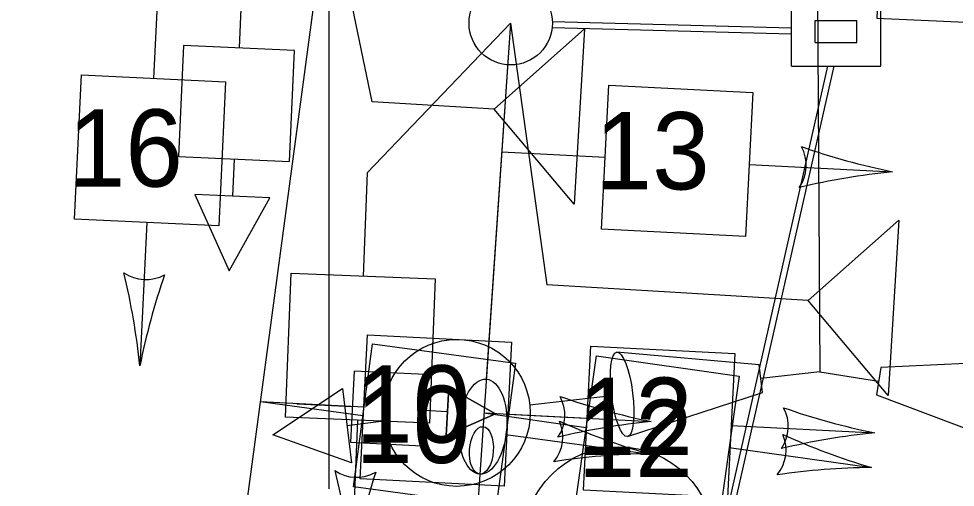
# Model space of a CAD drawing. Extents: x 647787 to 668496, y 640478 to 654412.
# Drawn here: x 659823.61 to 659862.98, y 647466.77 to 647486.47 of the extents above; entities that cross this region are included whole.
import ezdxf

# ---------------------------------------------------------------- set-up
doc = ezdxf.new("R2010")
doc.units = 0
for name, color, linetype in [('T_EXIST SIGNAL HEAD', 7, 'Continuous'), ('TEMP_SIGNAL POLES', 7, 'Continuous'), ('TEMP_SIGNAL_HEAD_STAGE 1A', 7, 'Continuous'), ('TEMP_SIGNAL_HEAD_STAGE 2', 7, 'Continuous'), ('TEMP_SIGNAL_HEAD_STAGE 2 SALEM', 7, 'Continuous'), ('TEMP_SIGNAL_HEAD_Stage 3', 7, 'Continuous'), ('TEMP_SIGNAL_HEAD_STAGE 5', 7, 'Continuous'), ('TEMP_SIGNAL_POLES_STAGE 1A', 7, 'Continuous'), ('TEMP_SIGNAL_POLES_STAGE 2', 7, 'Continuous'), ('TEMP_SIGNAL_POLES_STAGE 3', 7, 'Continuous'), ('TEMP_SIGNAL_POLES_STAGE 5', 7, 'Continuous'), ('TEXT_TEMP_SIGNAL_POLES_STAGE 2', 7, 'Continuous'), ('TEXT_TEMP_SIGNAL_POLES_STAGE 3', 7, 'Continuous'), ('TEXT_TEMP_SIGNAL_POLES_STAGE 4', 7, 'Continuous'), ('TEXT_TEMP_SIGNAL_POLES_STAGE 5', 7, 'Continuous')]:
    doc.layers.add(name, color=color, linetype=linetype)

msp = doc.modelspace()

# ---------------------------------------------------------------- linework, layer by layer
at = {"layer": 'T_EXIST SIGNAL HEAD'}
for points in [[(659837.714, 647471.654), (659837.562, 647468.658), (659840.558, 647468.506), (659840.71, 647471.502)], [(659837.714, 647471.654), (659837.562, 647468.658), (659840.558, 647468.506), (659840.71, 647471.502)], [(659837.714, 647471.654), (659837.562, 647468.658), (659840.558, 647468.506), (659840.71, 647471.502)], [(659837.714, 647471.654), (659837.562, 647468.658), (659840.558, 647468.506), (659840.71, 647471.502)], [(659843.646, 647469.851), (659841.684, 647470.963), (659841.581, 647468.943)], [(659843.646, 647469.851), (659841.684, 647470.963), (659841.581, 647468.943)], [(659843.646, 647469.851), (659841.684, 647470.963), (659841.581, 647468.943)], [(659843.646, 647469.851), (659841.684, 647470.963), (659841.581, 647468.943)]]:
    msp.add_lwpolyline(points, close=True, dxfattribs=at)
for points in [[(659841.581, 647468.943), (659841.684, 647470.963), (659843.646, 647469.851), (659841.581, 647468.943)], [(659841.581, 647468.943), (659841.684, 647470.963), (659843.646, 647469.851), (659841.581, 647468.943)], [(659841.581, 647468.943), (659841.684, 647470.963), (659843.646, 647469.851), (659841.581, 647468.943)], [(659841.581, 647468.943), (659841.684, 647470.963), (659843.646, 647469.851), (659841.581, 647468.943)], [(659835.296, 647470.275), (659837.638, 647470.156)], [(659835.296, 647470.275), (659837.638, 647470.156)], [(659835.296, 647470.275), (659837.638, 647470.156)], [(659835.296, 647470.275), (659837.638, 647470.156)], [(659840.634, 647470.004), (659841.632, 647469.953)], [(659840.634, 647470.004), (659841.632, 647469.953)], [(659840.634, 647470.004), (659841.632, 647469.953)], [(659840.634, 647470.004), (659841.632, 647469.953)]]:
    msp.add_lwpolyline(points, dxfattribs=at)
at = {"layer": 'TEMP_SIGNAL POLES'}
for points in [[(659857.129, 647496.616), (659857.292, 647471.616)], [(659857.129, 647496.616), (659857.292, 647471.616)], [(659857.129, 647496.616), (659857.292, 647471.616)], [(659857.131, 647496.618), (659857.294, 647471.618)]]:
    msp.add_lwpolyline(points, dxfattribs=at)
at = {"layer": 'TEMP_SIGNAL_HEAD_STAGE 1A'}
for p, q in [((659856.099, 647484.469), (659856.099, 647487.386)), ((659856.099, 647484.469), (659856.099, 647487.386)), ((659856.099, 647484.469), (659856.099, 647487.386)), ((659859.849, 647484.469), (659859.849, 647487.386)), ((659859.849, 647484.469), (659859.849, 647487.386)), ((659859.849, 647484.469), (659859.849, 647487.386)), ((659846.038, 647486.353), (659856.099, 647486.08)), ((659846.038, 647486.353), (659856.099, 647486.08)), ((659846.038, 647486.353), (659856.099, 647486.08)), ((659857.099, 647485.469), (659857.099, 647486.386)), ((659857.099, 647486.386), (659858.849, 647486.386)), ((659857.099, 647485.469), (659857.099, 647486.386)), ((659857.099, 647486.386), (659858.849, 647486.386)), ((659857.099, 647485.469), (659857.099, 647486.386)), ((659857.099, 647486.386), (659858.849, 647486.386)), ((659858.849, 647485.469), (659858.849, 647486.386)), ((659858.849, 647485.469), (659858.849, 647486.386)), ((659858.849, 647485.469), (659858.849, 647486.386)), ((659846.031, 647486.103), (659856.099, 647485.829)), ((659846.031, 647486.103), (659856.099, 647485.829)), ((659846.031, 647486.103), (659856.099, 647485.829)), ((659857.099, 647485.469), (659858.849, 647485.469)), ((659857.099, 647485.469), (659858.849, 647485.469)), ((659857.099, 647485.469), (659858.849, 647485.469)), ((659857.619, 647484.469), (659834.309, 647381.543)), ((659857.619, 647484.469), (659834.309, 647381.543)), ((659857.619, 647484.469), (659834.309, 647381.543)), ((659857.876, 647484.469), (659834.562, 647381.53)), ((659857.876, 647484.469), (659834.562, 647381.53)), ((659857.876, 647484.469), (659834.562, 647381.53)), ((659856.099, 647484.469), (659859.849, 647484.469)), ((659856.099, 647484.469), (659859.849, 647484.469)), ((659856.099, 647484.469), (659859.849, 647484.469))]:
    msp.add_line(p, q, dxfattribs=at)
at = {"layer": 'TEMP_SIGNAL_HEAD_STAGE 2'}
for p, q in [((659836.648, 647491.699), (659836.648, 647466.699)), ((659838.474, 647482.968), (659836.648, 647491.699)), ((659829.484, 647488.298), (659829.276, 647483.956)), ((659828.987, 647477.9), (659828.699, 647471.866)), ((659833.771, 647470.367), (659838.112, 647470.147)), ((659844.168, 647469.84), (659850.2, 647469.533))]:
    msp.add_line(p, q, dxfattribs=at)
msp.add_lwpolyline([(659843.591, 647482.659), (659847.402, 647486.037), (659846.958, 647478.67), (659843.591, 647482.659), (659838.474, 647482.968)], dxfattribs=at)
for points in [[(659826.248, 647484.101), (659832.305, 647483.811), (659832.016, 647477.755), (659825.958, 647478.045)], [(659837.959, 647467.118), (659838.266, 647473.175), (659844.321, 647472.868), (659844.014, 647466.811)]]:
    msp.add_lwpolyline(points, close=True, dxfattribs=at)
msp.add_circle((659848.829, 647464.468), 4, dxfattribs=at)
for centre, radius, start, end in [((659828.949, 647477.127), 1.629, 235.4173, 299.1119), ((659799.381, 647468.851), 29.472, 5.8729, 13.611), ((659857.594, 647466.069), 29.472, 160.9182, 168.6563), ((659844.94, 647469.8), 1.629, 325.2481, 28.9427), ((659856.083, 647498.412), 29.472, 250.749, 258.4871), ((659853.129, 647440.207), 29.472, 95.7037, 103.4418)]:
    msp.add_arc(centre, radius, start, end, dxfattribs=at)
at = {"layer": 'TEMP_SIGNAL_HEAD_STAGE 2 SALEM'}
for points in [[(659859.894, 647491.169), (659859.684, 647486.494), (659864.359, 647486.284), (659864.569, 647490.959)], [(659859.894, 647491.169), (659859.684, 647486.494), (659864.359, 647486.284), (659864.569, 647490.959)], [(659835.208, 647485.133), (659830.533, 647485.343), (659830.323, 647480.668), (659834.998, 647480.458)], [(659835.208, 647485.133), (659830.533, 647485.343), (659830.323, 647480.668), (659834.998, 647480.458)], [(659832.449, 647475.863), (659834.167, 647478.933), (659831.014, 647479.075)], [(659832.449, 647475.863), (659834.167, 647478.933), (659831.014, 647479.075)], [(659834.286, 647468.971), (659837.213, 647470.924), (659837.601, 647467.791)], [(659834.286, 647468.971), (659837.213, 647470.924), (659837.601, 647467.791)]]:
    msp.add_lwpolyline(points, close=True, dxfattribs=at)
for points in [[(659833.035, 647488.891), (659832.871, 647485.238)], [(659833.035, 647488.891), (659832.871, 647485.238)], [(659832.661, 647480.563), (659832.591, 647479.004)], [(659832.661, 647480.563), (659832.591, 647479.004)], [(659854.735, 647471.908), (659848.754, 647472.451)], [(659854.735, 647471.908), (659848.754, 647472.451)], [(659865.818, 647472.077), (659859.848, 647471.808)], [(659865.818, 647472.077), (659859.848, 647471.808)], [(659854.88, 647470.75), (659854.735, 647471.908)], [(659854.88, 647470.75), (659854.735, 647471.908)], [(659857.292, 647471.616), (659854.807, 647471.335)], [(659857.292, 647471.616), (659854.807, 647471.335)], [(659857.292, 647471.616), (659859.762, 647471.224)], [(659857.292, 647471.616), (659859.762, 647471.224)], [(659859.848, 647471.808), (659859.678, 647470.653)], [(659859.848, 647471.808), (659859.678, 647470.653)], [(659845.094, 647470.238), (659848.533, 647470.624)], [(659845.094, 647470.238), (659848.533, 647470.624)], [(659849.199, 647468.897), (659854.88, 647470.75)], [(659849.199, 647468.897), (659854.88, 647470.75)], [(659859.678, 647470.653), (659865.297, 647468.533)], [(659859.678, 647470.653), (659865.297, 647468.533)], [(659838.955, 647469.549), (659837.407, 647469.357)], [(659838.955, 647469.549), (659837.407, 647469.357)]]:
    msp.add_lwpolyline(points, dxfattribs=at)
msp.add_circle((659842.025, 647469.894), 3.089, dxfattribs=at)
msp.add_circle((659842.025, 647469.894), 3.089, dxfattribs=at)
msp.add_ellipse((659848.976, 647470.674), major_axis=(-0.222, 1.777), ratio=0.249111, dxfattribs=at)
msp.add_ellipse((659848.976, 647470.674), major_axis=(-0.222, 1.777), ratio=0.249111, dxfattribs=at)
at = {"layer": 'TEMP_SIGNAL_HEAD_Stage 3'}
for p, q in [((659836.648, 647491.699), (659836.648, 647466.699)), ((659838.474, 647482.968), (659836.648, 647491.699)), ((659833.771, 647470.367), (659838.079, 647469.789)), ((659844.088, 647468.983), (659850.075, 647468.179))]:
    msp.add_line(p, q, dxfattribs=at)
msp.add_lwpolyline([(659843.591, 647482.659), (659847.402, 647486.037), (659846.958, 647478.67), (659843.591, 647482.659), (659838.474, 647482.968)], dxfattribs=at)
msp.add_lwpolyline([(659837.676, 647466.784), (659838.483, 647472.794), (659844.492, 647471.988), (659843.685, 647465.977)], close=True, dxfattribs=at)
for centre, radius, start, end in [((659844.855, 647468.879), 1.629, 320.5102, 24.2048), ((659858.323, 647496.473), 29.472, 246.0111, 253.7492), ((659850.572, 647438.711), 29.472, 90.9658, 98.7039)]:
    msp.add_arc(centre, radius, start, end, dxfattribs=at)
at = {"layer": 'TEMP_SIGNAL_HEAD_STAGE 5'}
for p, q in [((659844.29, 647486.275), (659845.808, 647475.278)), ((659844.29, 647486.275), (659845.808, 647475.278)), ((659843.919, 647480.866), (659848.261, 647480.646)), ((659854.316, 647480.338), (659860.349, 647480.032)), ((659851.678, 647474.924), (659845.808, 647475.278)), ((659851.678, 647474.924), (659845.808, 647475.278)), ((659843.168, 647469.89), (659847.472, 647469.285)), ((659843.168, 647469.89), (659847.509, 647469.67)), ((659853.564, 647469.362), (659859.597, 647469.056)), ((659853.476, 647468.441), (659859.458, 647467.6))]:
    msp.add_line(p, q, dxfattribs=at)
for points in [[(659848.107, 647477.617), (659848.414, 647483.674), (659854.47, 647483.367), (659854.162, 647477.31)], [(659847.355, 647466.641), (659847.663, 647472.698), (659853.718, 647472.391), (659853.411, 647466.334)], [(659847.05, 647466.282), (659847.894, 647472.287), (659853.898, 647471.443), (659853.054, 647465.438)]]:
    msp.add_lwpolyline(points, close=True, dxfattribs=at)
msp.add_lwpolyline([(659856.796, 647474.615), (659860.606, 647477.993), (659860.162, 647470.626), (659856.796, 647474.615), (659851.678, 647474.924)], dxfattribs=at)
msp.add_lwpolyline([(659856.796, 647474.615), (659860.606, 647477.993), (659860.162, 647470.626), (659856.796, 647474.615), (659851.678, 647474.924)], dxfattribs=at)
for centre, radius, start, end in [((659855.089, 647480.298), 1.629, 325.2481, 28.9427), ((659866.231, 647508.911), 29.472, 250.749, 258.4871), ((659863.278, 647450.705), 29.472, 95.7037, 103.4418), ((659854.337, 647469.322), 1.629, 325.2481, 28.9427), ((659865.479, 647497.935), 29.472, 250.749, 258.4871), ((659854.242, 647468.332), 1.629, 320.1497, 23.8443), ((659862.526, 647439.729), 29.472, 95.7037, 103.4418), ((659867.883, 647495.841), 29.472, 245.6506, 253.3887), ((659859.769, 647438.128), 29.472, 90.6053, 98.3434)]:
    msp.add_arc(centre, radius, start, end, dxfattribs=at)
at = {"layer": 'TEMP_SIGNAL_POLES_STAGE 1A'}
for p, q in [((659838.26, 647479.991), (659844.29, 647486.275)), ((659844.29, 647486.275), (659840.737, 647434.397)), ((659844.29, 647486.275), (659843.265, 647471.31)), ((659844.29, 647486.275), (659845.808, 647475.278)), ((659843.919, 647480.866), (659848.261, 647480.646)), ((659854.316, 647480.338), (659860.349, 647480.032)), ((659838.26, 647479.991), (659838.089, 647475.647)), ((659851.678, 647474.924), (659845.808, 647475.278)), ((659843.168, 647469.89), (659847.509, 647469.67)), ((659837.85, 647469.589), (659837.612, 647463.553)), ((659853.564, 647469.362), (659859.597, 647469.056))]:
    msp.add_line(p, q, dxfattribs=at)
for points in [[(659848.107, 647477.617), (659848.414, 647483.674), (659854.47, 647483.367), (659854.162, 647477.31)], [(659835.059, 647475.766), (659841.119, 647475.527), (659840.88, 647469.469), (659834.82, 647469.708)], [(659847.355, 647466.641), (659847.663, 647472.698), (659853.718, 647472.391), (659853.411, 647466.334)]]:
    msp.add_lwpolyline(points, close=True, dxfattribs=at)
msp.add_lwpolyline([(659856.796, 647474.615), (659860.606, 647477.993), (659860.162, 647470.626), (659856.796, 647474.615), (659851.678, 647474.924)], dxfattribs=at)
msp.add_circle((659844.293, 647486.274), 1.75, dxfattribs=at)
for centre, radius, start, end in [((659855.089, 647480.298), 1.629, 325.2481, 28.9427), ((659866.231, 647508.911), 29.472, 250.749, 258.4871), ((659863.278, 647450.705), 29.472, 95.7037, 103.4418), ((659854.337, 647469.322), 1.629, 325.2481, 28.9427), ((659865.479, 647497.935), 29.472, 250.749, 258.4871), ((659862.526, 647439.729), 29.472, 95.7037, 103.4418), ((659837.818, 647468.815), 1.629, 235.8929, 299.5875), ((659808.319, 647460.294), 29.472, 6.3485, 14.0866), ((659866.554, 647457.996), 29.472, 161.3938, 169.1319)]:
    msp.add_arc(centre, radius, start, end, dxfattribs=at)
for centre, major_axis in [((659843.128, 647469.315), (-0.137, -1.995)), ((659843.06, 647468.317), (0.068, 0.998))]:
    msp.add_ellipse(centre, major_axis=major_axis, ratio=0.5, dxfattribs=at)
at = {"layer": 'TEMP_SIGNAL_POLES_STAGE 2'}
msp.add_line((659823.607, 647395.017), (659836.648, 647491.699), dxfattribs=at)
at = {"layer": 'TEMP_SIGNAL_POLES_STAGE 3'}
msp.add_line((659823.607, 647395.017), (659836.648, 647491.699), dxfattribs=at)
at = {"layer": 'TEMP_SIGNAL_POLES_STAGE 5'}
for q in [(659840.737, 647434.397), (659840.737, 647434.397), (659843.265, 647471.31), (659843.265, 647471.31)]:
    msp.add_line((659844.29, 647486.275), q, dxfattribs=at)
msp.add_circle((659844.293, 647486.274), 1.75, dxfattribs=at)
msp.add_circle((659844.293, 647486.274), 1.75, dxfattribs=at)
for centre, major_axis in [((659843.128, 647469.315), (-0.137, -1.995)), ((659843.128, 647469.315), (-0.137, -1.995)), ((659843.06, 647468.317), (0.068, 0.998)), ((659843.06, 647468.317), (0.068, 0.998))]:
    msp.add_ellipse(centre, major_axis=major_axis, ratio=0.5, dxfattribs=at)

# ---------------------------------------------------------------- texts
at = {"layer": 'TEXT_TEMP_SIGNAL_POLES_STAGE 2'}
for s, p in [('16', (659825.672, 647479.405)), ('10', (659837.762, 647468.645))]:
    msp.add_text(s, height=3.25, dxfattribs=at).set_placement(p)
at = {"layer": 'TEXT_TEMP_SIGNAL_POLES_STAGE 3'}
msp.add_text('10', height=3.25, dxfattribs=at).set_placement((659837.762, 647467.785))
at = {"layer": 'TEXT_TEMP_SIGNAL_POLES_STAGE 4'}
msp.add_text('12', height=3.25, dxfattribs=at).set_placement((659847.111, 647467.199))
at = {"layer": 'TEXT_TEMP_SIGNAL_POLES_STAGE 5'}
for s, p in [('13', (659847.825, 647479.288)), ('12', (659847.111, 647468.127))]:
    msp.add_text(s, height=3.25, dxfattribs=at).set_placement(p)

doc.saveas('drawing.dxf')
